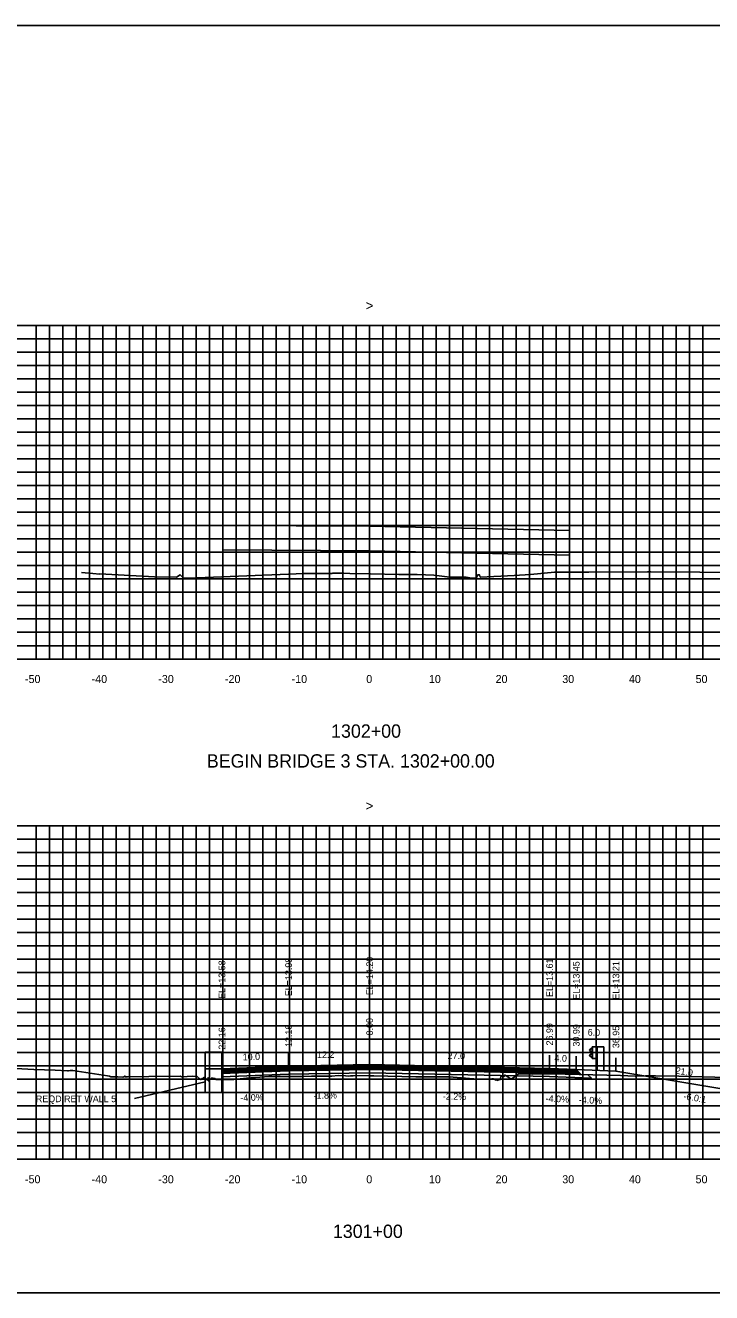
# Model space of a CAD drawing. Extents: x 1797714 to 1804825, y 249015 to 250269.
# Drawn here: x 1802579.4 to 1802682.3, y 250079.4 to 250269.4 of the extents above; entities that cross this region are included whole.
import ezdxf

# ---------------------------------------------------------------- set-up
doc = ezdxf.new("R2010")
doc.units = 0
for name, color, linetype in [('1', 7, 'Continuous'), ('10', 7, 'Continuous'), ('3', 7, 'Continuous'), ('4', 7, 'Continuous'), ('60', 7, 'Continuous'), ('BASE', 7, 'Continuous'), ('BRG-DECK', 7, 'Continuous'), ('CL-CNST', 7, 'Continuous'), ('Level 1', 7, 'Continuous'), ('Level 62', 7, 'Continuous'), ('LOWER BINDER', 7, 'Continuous'), ('M-ROADS', 7, 'Continuous'), ('UPPER BINDER', 7, 'Continuous'), ('WEARING', 7, 'Continuous')]:
    doc.layers.add(name, color=color, linetype=linetype)

msp = doc.modelspace()

# ---------------------------------------------------------------- linework, layer by layer
for p, q in [((1802661, 250193.58), (1802661, 250195.58)), ((1802608.84, 250113.01), (1802608.84, 250115.01)), ((1802618.84, 250113.41), (1802618.84, 250115.41)), ((1802631, 250113.63), (1802631, 250115.63)), ((1802658, 250113.04), (1802658, 250115.04)), ((1802662, 250112.88), (1802662, 250114.88)), ((1802667.95, 250112.64), (1802667.95, 250114.64))]:
    msp.add_line(p, q)
msp.add_lwpolyline([(1802481, 250079.43), (1802781, 250079.43), (1802781, 250269.43), (1802481, 250269.43)], close=True)
at = {"layer": '3'}
msp.add_line((1802595.75, 250108.54), (1802606.34, 250111.02), dxfattribs=at)
at = {"layer": '60'}
for p, q in [((1802481, 250174.43), (1802781, 250174.43)), ((1802581, 250174.37), (1802581, 250174.43)), ((1802591, 250174.37), (1802591, 250174.43)), ((1802601, 250174.37), (1802601, 250174.43)), ((1802611, 250174.37), (1802611, 250174.43)), ((1802621, 250174.37), (1802621, 250174.43)), ((1802631, 250174.37), (1802631, 250174.43)), ((1802641, 250174.37), (1802641, 250174.43)), ((1802651, 250174.37), (1802651, 250174.43)), ((1802661, 250174.37), (1802661, 250174.43)), ((1802671, 250174.37), (1802671, 250174.43)), ((1802681, 250174.37), (1802681, 250174.43)), ((1802481, 250099.43), (1802781, 250099.43)), ((1802581, 250099.37), (1802581, 250099.43)), ((1802591, 250099.37), (1802591, 250099.43)), ((1802601, 250099.37), (1802601, 250099.43)), ((1802611, 250099.37), (1802611, 250099.43)), ((1802621, 250099.37), (1802621, 250099.43)), ((1802631, 250099.37), (1802631, 250099.43)), ((1802641, 250099.37), (1802641, 250099.43)), ((1802651, 250099.37), (1802651, 250099.43)), ((1802661, 250099.37), (1802661, 250099.43)), ((1802671, 250099.37), (1802671, 250099.43)), ((1802681, 250099.37), (1802681, 250099.43))]:
    msp.add_line(p, q, dxfattribs=at)
at = {"layer": 'BASE'}
msp.add_lwpolyline([(1802608.84, 250112.29), (1802618.84, 250112.69), (1802631, 250112.91), (1802658, 250112.32), (1802662.75, 250112.13), (1802663.75, 250112.09), (1802664.27, 250111.57), (1802658, 250111.82), (1802631, 250112.41), (1802618.84, 250112.19), (1802608.84, 250111.79)], close=True, dxfattribs=at)
at = {"layer": 'BRG-DECK'}
msp.add_lwpolyline([(1802661, 250190), (1802661, 250193.68), (1802661, 250193.68), (1802631, 250194.34), (1802609, 250194.46), (1802609, 250190.78), (1802631, 250190.66), (1802661, 250190)], close=True, dxfattribs=at)
at = {"layer": 'CL-CNST'}
for points in [[(1802609, 250194.46), (1802631, 250194.34), (1802661, 250193.68)], [(1802608.84, 250113.01), (1802618.84, 250113.41), (1802631, 250113.63), (1802658, 250113.04), (1802662, 250112.88), (1802667.95, 250112.64), (1802688.95, 250109.14), (1802692.95, 250109.14), (1802703.12, 250111.68)]]:
    msp.add_lwpolyline(points, dxfattribs=at)
for points in [[(1802608.84, 250113.01), (1802606.34, 250113.01), (1802606.34, 250115.51), (1802608.84, 250115.51)], [(1802606.34, 250109.43), (1802608.84, 250109.43), (1802608.84, 250113.01), (1802606.34, 250113.01)]]:
    msp.add_lwpolyline(points, close=True, dxfattribs=at)
at = {"layer": 'Level 1'}
for p, q in [((1802664.38, 250116.13), (1802664.01, 250115.83)), ((1802664.38, 250116.28), (1802664.38, 250114.53)), ((1802666.13, 250116.28), (1802664.38, 250116.28)), ((1802664.43, 250116.28), (1802664.43, 250114.53)), ((1802665.08, 250116.28), (1802665.08, 250114.53)), ((1802665.13, 250116.28), (1802665.13, 250112.75)), ((1802666.13, 250116.28), (1802666.13, 250112.71)), ((1802664.01, 250115.76), (1802664.38, 250115.47)), ((1802664.38, 250115.33), (1802664.01, 250115.04)), ((1802664.01, 250114.96), (1802664.38, 250114.68)), ((1802665.13, 250114.53), (1802664.38, 250114.53))]:
    msp.add_line(p, q, dxfattribs=at)
for centre in [(1802664.05, 250115.8), (1802664.05, 250115)]:
    msp.add_arc(centre, 0.05, 135, 226.6208, dxfattribs=at)
at = {"layer": 'Level 62'}
for p, q in [((1802481, 250224.43), (1802781, 250224.43)), ((1802581, 250174.43), (1802581, 250224.43)), ((1802583, 250174.43), (1802583, 250224.43)), ((1802585, 250174.43), (1802585, 250224.43)), ((1802587, 250174.43), (1802587, 250224.43)), ((1802589, 250174.43), (1802589, 250224.43)), ((1802591, 250174.43), (1802591, 250224.43)), ((1802593, 250174.43), (1802593, 250224.43)), ((1802595, 250174.43), (1802595, 250224.43)), ((1802597, 250174.43), (1802597, 250224.43)), ((1802599, 250174.43), (1802599, 250224.43)), ((1802601, 250174.43), (1802601, 250224.43)), ((1802603, 250174.43), (1802603, 250224.43)), ((1802605, 250174.43), (1802605, 250224.43)), ((1802607, 250174.43), (1802607, 250224.43)), ((1802609, 250174.43), (1802609, 250224.43)), ((1802611, 250174.43), (1802611, 250224.43)), ((1802613, 250174.43), (1802613, 250224.43)), ((1802615, 250174.43), (1802615, 250224.43)), ((1802617, 250174.43), (1802617, 250224.43)), ((1802619, 250174.43), (1802619, 250224.43)), ((1802621, 250174.43), (1802621, 250224.43)), ((1802623, 250174.43), (1802623, 250224.43)), ((1802625, 250174.43), (1802625, 250224.43)), ((1802627, 250174.43), (1802627, 250224.43)), ((1802629, 250174.43), (1802629, 250224.43)), ((1802631, 250174.43), (1802631, 250224.43)), ((1802633, 250174.43), (1802633, 250224.43)), ((1802635, 250174.43), (1802635, 250224.43)), ((1802637, 250174.43), (1802637, 250224.43)), ((1802639, 250174.43), (1802639, 250224.43)), ((1802641, 250174.43), (1802641, 250224.43)), ((1802643, 250174.43), (1802643, 250224.43)), ((1802645, 250174.43), (1802645, 250224.43)), ((1802647, 250174.43), (1802647, 250224.43)), ((1802649, 250174.43), (1802649, 250224.43)), ((1802651, 250174.43), (1802651, 250224.43)), ((1802653, 250174.43), (1802653, 250224.43)), ((1802655, 250174.43), (1802655, 250224.43)), ((1802657, 250174.43), (1802657, 250224.43)), ((1802659, 250174.43), (1802659, 250224.43)), ((1802661, 250174.43), (1802661, 250224.43)), ((1802663, 250174.43), (1802663, 250224.43)), ((1802665, 250174.43), (1802665, 250224.43)), ((1802667, 250174.43), (1802667, 250224.43)), ((1802669, 250174.43), (1802669, 250224.43)), ((1802671, 250174.43), (1802671, 250224.43)), ((1802673, 250174.43), (1802673, 250224.43)), ((1802675, 250174.43), (1802675, 250224.43)), ((1802677, 250174.43), (1802677, 250224.43)), ((1802679, 250174.43), (1802679, 250224.43)), ((1802681, 250174.43), (1802681, 250224.43)), ((1802481, 250222.43), (1802781, 250222.43)), ((1802481, 250220.43), (1802781, 250220.43)), ((1802481, 250218.43), (1802781, 250218.43)), ((1802481, 250216.43), (1802781, 250216.43)), ((1802481, 250214.43), (1802781, 250214.43)), ((1802481, 250212.43), (1802781, 250212.43)), ((1802481, 250210.43), (1802781, 250210.43)), ((1802481, 250208.43), (1802781, 250208.43)), ((1802481, 250206.43), (1802781, 250206.43)), ((1802481, 250204.43), (1802781, 250204.43)), ((1802481, 250202.43), (1802781, 250202.43)), ((1802481, 250200.43), (1802781, 250200.43)), ((1802481, 250198.43), (1802781, 250198.43)), ((1802481, 250196.43), (1802781, 250196.43)), ((1802481, 250194.43), (1802781, 250194.43)), ((1802481, 250192.43), (1802781, 250192.43)), ((1802481, 250190.43), (1802781, 250190.43)), ((1802481, 250188.43), (1802781, 250188.43)), ((1802481, 250186.43), (1802781, 250186.43)), ((1802481, 250184.43), (1802781, 250184.43)), ((1802481, 250182.43), (1802781, 250182.43)), ((1802481, 250180.43), (1802781, 250180.43)), ((1802481, 250178.43), (1802781, 250178.43)), ((1802481, 250176.43), (1802781, 250176.43)), ((1802481, 250174.43), (1802781, 250174.43)), ((1802481, 250149.43), (1802781, 250149.43)), ((1802581, 250099.43), (1802581, 250149.43)), ((1802583, 250099.43), (1802583, 250149.43)), ((1802585, 250099.43), (1802585, 250149.43)), ((1802587, 250099.43), (1802587, 250149.43)), ((1802589, 250099.43), (1802589, 250149.43)), ((1802591, 250099.43), (1802591, 250149.43)), ((1802593, 250099.43), (1802593, 250149.43)), ((1802595, 250099.43), (1802595, 250149.43)), ((1802597, 250099.43), (1802597, 250149.43)), ((1802599, 250099.43), (1802599, 250149.43)), ((1802601, 250099.43), (1802601, 250149.43)), ((1802603, 250099.43), (1802603, 250149.43)), ((1802605, 250099.43), (1802605, 250149.43)), ((1802607, 250099.43), (1802607, 250149.43)), ((1802609, 250099.43), (1802609, 250149.43)), ((1802611, 250099.43), (1802611, 250149.43)), ((1802613, 250099.43), (1802613, 250149.43)), ((1802615, 250099.43), (1802615, 250149.43)), ((1802617, 250099.43), (1802617, 250149.43)), ((1802619, 250099.43), (1802619, 250149.43)), ((1802621, 250099.43), (1802621, 250149.43)), ((1802623, 250099.43), (1802623, 250149.43)), ((1802625, 250099.43), (1802625, 250149.43)), ((1802627, 250099.43), (1802627, 250149.43)), ((1802629, 250099.43), (1802629, 250149.43)), ((1802631, 250099.43), (1802631, 250149.43)), ((1802633, 250099.43), (1802633, 250149.43)), ((1802635, 250099.43), (1802635, 250149.43)), ((1802637, 250099.43), (1802637, 250149.43)), ((1802639, 250099.43), (1802639, 250149.43)), ((1802641, 250099.43), (1802641, 250149.43)), ((1802643, 250099.43), (1802643, 250149.43)), ((1802645, 250099.43), (1802645, 250149.43)), ((1802647, 250099.43), (1802647, 250149.43)), ((1802649, 250099.43), (1802649, 250149.43)), ((1802651, 250099.43), (1802651, 250149.43)), ((1802653, 250099.43), (1802653, 250149.43)), ((1802655, 250099.43), (1802655, 250149.43)), ((1802657, 250099.43), (1802657, 250149.43)), ((1802659, 250099.43), (1802659, 250149.43)), ((1802661, 250099.43), (1802661, 250149.43)), ((1802663, 250099.43), (1802663, 250149.43)), ((1802665, 250099.43), (1802665, 250149.43)), ((1802667, 250099.43), (1802667, 250149.43)), ((1802669, 250099.43), (1802669, 250149.43)), ((1802671, 250099.43), (1802671, 250149.43)), ((1802673, 250099.43), (1802673, 250149.43)), ((1802675, 250099.43), (1802675, 250149.43)), ((1802677, 250099.43), (1802677, 250149.43)), ((1802679, 250099.43), (1802679, 250149.43)), ((1802681, 250099.43), (1802681, 250149.43)), ((1802481, 250147.43), (1802781, 250147.43)), ((1802481, 250145.43), (1802781, 250145.43)), ((1802481, 250143.43), (1802781, 250143.43)), ((1802481, 250141.43), (1802781, 250141.43)), ((1802481, 250139.43), (1802781, 250139.43)), ((1802481, 250137.43), (1802781, 250137.43)), ((1802481, 250135.43), (1802781, 250135.43)), ((1802481, 250133.43), (1802781, 250133.43)), ((1802481, 250131.43), (1802781, 250131.43)), ((1802481, 250129.43), (1802781, 250129.43)), ((1802481, 250127.43), (1802781, 250127.43)), ((1802481, 250125.43), (1802781, 250125.43)), ((1802481, 250123.43), (1802781, 250123.43)), ((1802481, 250121.43), (1802781, 250121.43)), ((1802481, 250119.43), (1802781, 250119.43)), ((1802481, 250117.43), (1802781, 250117.43)), ((1802481, 250115.43), (1802781, 250115.43)), ((1802481, 250113.43), (1802781, 250113.43)), ((1802481, 250111.43), (1802781, 250111.43)), ((1802481, 250109.43), (1802781, 250109.43)), ((1802481, 250107.43), (1802781, 250107.43)), ((1802481, 250105.43), (1802781, 250105.43)), ((1802481, 250103.43), (1802781, 250103.43)), ((1802481, 250101.43), (1802781, 250101.43)), ((1802481, 250099.43), (1802781, 250099.43))]:
    msp.add_line(p, q, dxfattribs=at)
at = {"layer": 'LOWER BINDER'}
for points in [[(1802618.84, 250113.07), (1802631, 250113.29), (1802658, 250112.7), (1802662.35, 250112.53), (1802662.55, 250112.33), (1802658, 250112.51), (1802631, 250113.1), (1802618.84, 250112.88), (1802608.84, 250112.48), (1802608.84, 250112.67)], [(1802618.84, 250112.88), (1802631, 250113.1), (1802658, 250112.51), (1802662.55, 250112.33), (1802662.75, 250112.13), (1802658, 250112.32), (1802631, 250112.91), (1802618.84, 250112.69), (1802608.84, 250112.29), (1802608.84, 250112.48)]]:
    msp.add_lwpolyline(points, close=True, dxfattribs=at)
at = {"layer": 'M-ROADS'}
for points in [[(1802587.76, 250187.41), (1802589.48, 250187.26), (1802590.51, 250187.17), (1802590.52, 250187.2), (1802598.72, 250186.76), (1802602.03, 250186.71), (1802602.56, 250187.07), (1802602.82, 250186.82), (1802603.06, 250186.57), (1802603.83, 250186.57), (1802618.82, 250187.13), (1802621.11, 250187.24), (1802622.4, 250187.26), (1802623.07, 250187.27), (1802624.64, 250187.27), (1802625.34, 250187.27), (1802625.46, 250187.28), (1802625.7, 250187.28), (1802627.15, 250187.28), (1802628.05, 250187.27), (1802631.14, 250187.19), (1802635.39, 250187.11), (1802636.43, 250187.12), (1802638.13, 250187.11), (1802640.63, 250187), (1802643.03, 250186.68), (1802643.69, 250186.68), (1802645.09, 250186.68), (1802645.13, 250186.68), (1802645.15, 250186.68), (1802645.5, 250186.68), (1802646.34, 250186.54), (1802646.38, 250186.54), (1802646.65, 250186.53), (1802646.76, 250186.55), (1802646.97, 250186.57), (1802647, 250186.55), (1802647.14, 250186.88), (1802647.21, 250187.03), (1802647.24, 250187.03), (1802647.33, 250187.03), (1802647.49, 250187.03), (1802647.55, 250186.83), (1802647.56, 250186.78), (1802647.6, 250186.74), (1802647.63, 250186.68), (1802652.68, 250186.97), (1802655.14, 250187.11), (1802658.72, 250187.43), (1802658.81, 250187.43), (1802659.16, 250187.43), (1802661.43, 250187.44), (1802661.49, 250187.44), (1802663.87, 250187.44), (1802672.67, 250187.48), (1802672.79, 250187.48), (1802673.17, 250187.48), (1802680.54, 250187.46), (1802684.6, 250187.42)], [(1802571.46, 250113.37), (1802580.63, 250112.87), (1802583.84, 250112.79), (1802585.66, 250112.71), (1802585.85, 250112.71), (1802586.09, 250112.73), (1802586.47, 250112.73), (1802591.7, 250111.92), (1802592, 250111.87), (1802592.2, 250111.8), (1802592.83, 250111.79), (1802593.22, 250111.78), (1802593.97, 250111.76), (1802594.14, 250111.79), (1802594.26, 250111.93), (1802594.33, 250111.78), (1802594.69, 250111.78), (1802597.88, 250111.83), (1802602.56, 250111.87), (1802602.84, 250111.78), (1802604.44, 250111.87), (1802605.05, 250111.84), (1802605.11, 250111.84), (1802605.64, 250111.4), (1802605.68, 250111.4), (1802605.76, 250111.46), (1802605.82, 250111.48), (1802605.86, 250111.54), (1802605.9, 250111.54), (1802605.93, 250111.52), (1802605.98, 250111.55), (1802606, 250111.56), (1802606.02, 250111.57), (1802606.03, 250111.59), (1802606.04, 250111.6), (1802606.07, 250111.61), (1802606.08, 250111.61), (1802606.09, 250111.62), (1802606.26, 250111.72), (1802606.41, 250111.42), (1802606.43, 250111.38), (1802606.68, 250111.33), (1802606.75, 250111.27), (1802606.75, 250111.26), (1802606.76, 250111.64), (1802606.76, 250111.24), (1802606.82, 250111.18), (1802606.94, 250111.24), (1802607.34, 250111.63), (1802607.76, 250111.56), (1802608, 250111.4), (1802608.27, 250111.41), (1802608.86, 250111.32), (1802609.84, 250111.41), (1802610.61, 250111.41), (1802612.52, 250111.57), (1802615.9, 250111.85), (1802617.19, 250111.84), (1802618.21, 250111.83), (1802618.38, 250111.83), (1802618.56, 250111.84), (1802619.64, 250111.83), (1802620.88, 250111.83), (1802622.28, 250111.89), (1802623.11, 250111.9), (1802625.23, 250111.9), (1802625.32, 250111.91), (1802626.3, 250111.97), (1802627.38, 250111.92), (1802627.82, 250111.91), (1802628.13, 250111.92), (1802628.55, 250111.94), (1802628.86, 250111.98), (1802631.15, 250111.96), (1802631.27, 250111.96), (1802631.63, 250111.95), (1802637.91, 250111.79), (1802640.07, 250111.77), (1802640.14, 250111.77), (1802640.16, 250111.77), (1802640.49, 250111.8), (1802642.57, 250111.79), (1802642.89, 250111.79), (1802643.51, 250111.74), (1802647.22, 250111.46), (1802649.32, 250111.5), (1802649.55, 250111.5), (1802649.88, 250111.34), (1802650, 250111.29), (1802650.08, 250111.35), (1802650.21, 250111.26), (1802650.23, 250111.27), (1802650.59, 250111.38), (1802650.64, 250111.54), (1802650.66, 250111.82), (1802650.78, 250111.91), (1802650.78, 250111.91), (1802650.98, 250111.89), (1802651.14, 250111.86), (1802651.16, 250111.82), (1802651.17, 250111.84), (1802651.25, 250111.98), (1802651.28, 250112.04), (1802651.48, 250111.93), (1802651.62, 250111.84), (1802652.22, 250111.46), (1802653.24, 250112.16), (1802653.39, 250112.25), (1802655.49, 250112.2), (1802655.68, 250112.26), (1802656.16, 250112.26), (1802657.79, 250112.26), (1802658.26, 250112.26), (1802668.65, 250111.98), (1802670.86, 250111.91), (1802672.39, 250111.94), (1802673.17, 250111.94), (1802673.34, 250111.94), (1802673.91, 250111.94), (1802677.38, 250111.87), (1802684.57, 250111.68)]]:
    msp.add_lwpolyline(points, dxfattribs=at)
at = {"layer": 'UPPER BINDER'}
msp.add_lwpolyline([(1802658, 250112.7), (1802662.35, 250112.53), (1802662.15, 250112.72), (1802658, 250112.89), (1802631, 250113.48), (1802618.84, 250113.26), (1802608.84, 250112.86), (1802608.84, 250112.67), (1802618.84, 250113.07), (1802631, 250113.29)], close=True, dxfattribs=at)
at = {"layer": 'WEARING'}
msp.add_lwpolyline([(1802658, 250112.89), (1802662.15, 250112.72), (1802662, 250112.88), (1802658, 250113.04), (1802631, 250113.63), (1802618.84, 250113.41), (1802608.84, 250113.01), (1802608.84, 250112.86), (1802618.84, 250113.26), (1802631, 250113.48)], close=True, dxfattribs=at)

# ---------------------------------------------------------------- texts
msp.add_text('-6.0:1', height=1, rotation=350.5377).set_placement((1802678.04, 250108.43))
at = {"layer": '1'}
for s, p in [('1302+00', (1802625.22, 250162.63)), ('BEGIN BRIDGE 3 STA. 1302+00.00', (1802606.58, 250158.15)), ('1301+00', (1802625.49, 250087.63))]:
    msp.add_text(s, height=2, dxfattribs=at).set_placement(p)
at = {"layer": '10'}
for s, p in [('-50', (1802579.3, 250170.83)), ('-40', (1802589.3, 250170.83)), ('-30', (1802599.3, 250170.83)), ('-20', (1802609.3, 250170.83)), ('-10', (1802619.3, 250170.83)), ('0', (1802630.5, 250170.83)), ('10', (1802639.9, 250170.83)), ('20', (1802649.9, 250170.83)), ('30', (1802659.9, 250170.83)), ('40', (1802669.9, 250170.83)), ('50', (1802679.9, 250170.83)), ('-50', (1802579.3, 250095.83)), ('-40', (1802589.3, 250095.83)), ('-30', (1802599.3, 250095.83)), ('-20', (1802609.3, 250095.83)), ('-10', (1802619.3, 250095.83)), ('0', (1802630.5, 250095.83)), ('10', (1802639.9, 250095.83)), ('20', (1802649.9, 250095.83)), ('30', (1802659.9, 250095.83)), ('40', (1802669.9, 250095.83)), ('50', (1802679.9, 250095.83))]:
    msp.add_text(s, height=1.2, dxfattribs=at).set_placement(p)
at = {"layer": '3'}
for s, p in [('EL=13.98', (1802619.34, 250123.88)), ('EL=14.20', (1802631.5, 250124.03)), ('EL=13.61', (1802658.5, 250123.76)), ('EL=13.58', (1802609.34, 250123.48)), ('EL=13.45', (1802662.5, 250123.35)), ('EL=13.21', (1802668.45, 250123.37)), ('0.00', (1802631.5, 250118)), ('-22.16', (1802609.34, 250115.42)), ('-12.16', (1802619.34, 250115.82)), ('26.99', (1802658.5, 250116.49)), ('30.99', (1802662.5, 250116.33)), ('36.95', (1802668.45, 250116.09))]:
    msp.add_text(s, height=1, rotation=90, dxfattribs=at).set_placement(p)
msp.add_text('REQD RET WALL 5', height=1, dxfattribs=at).set_placement((1802580.93, 250107.99))
at = {"layer": '4'}
for s, rotation, p in [('6.0', 357.7094, (1802663.7, 250117.98)), ('10.0', 2.2906, (1802611.98, 250114.24)), ('12.2', 1.0549, (1802623.12, 250114.59)), ('27.0', 358.7397, (1802642.7, 250114.48)), ('4.0', 357.7094, (1802658.72, 250114.11)), ('21.0', 350.5377, (1802676.84, 250112.28)), ('-4.0%', 2.2906, (1802611.63, 250108.12)), ('-1.8%', 1.0549, (1802622.6, 250108.48)), ('-2.2%', 358.7397, (1802641.98, 250108.39)), ('-4.0%', 357.7094, (1802657.39, 250108.06)), ('-4.0%', 357.7094, (1802662.37, 250107.86))]:
    msp.add_text(s, height=1, rotation=rotation, dxfattribs=at).set_placement(p)
at = {"layer": '60'}
for p in [(1802630.39, 250226.68), (1802630.39, 250151.68)]:
    msp.add_text('>', height=1.5, dxfattribs=at).set_placement(p)

doc.saveas('drawing.dxf')
